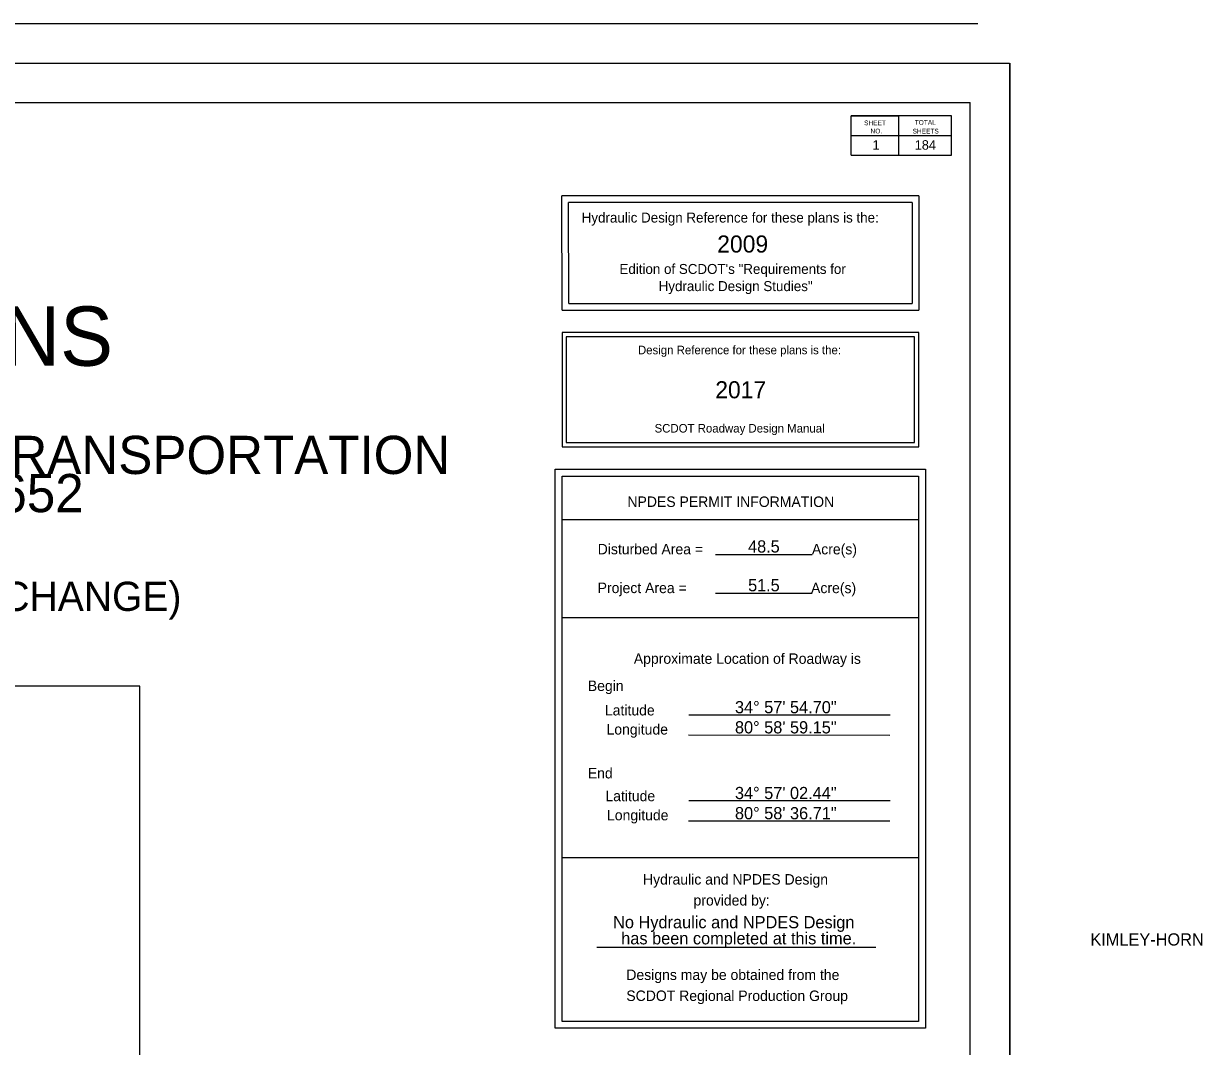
# Model space of a CAD drawing. Extents: x 1524103 to 2096450, y 1024229 to 1162569.
# Drawn here: x 2064966 to 2096450, y 1135259 to 1162569 of the extents above; entities that cross this region are included whole.
import ezdxf

# ---------------------------------------------------------------- set-up
doc = ezdxf.new("R2010")
doc.units = 0
for name, color, linetype in [('GN_TitleSheetMap', 7, 'Continuous'), ('RD_SHT_Bndy', 7, 'Continuous'), ('RD_SHT_IplotShp', 7, 'Continuous'), ('RD_SHT_Snap', 7, 'Continuous'), ('RD_SHT_TX', 7, 'Continuous'), ('RD_TX_TitleSht', 7, 'Continuous')]:
    doc.layers.add(name, color=color, linetype=linetype)

msp = doc.modelspace()

# ---------------------------------------------------------------- linework, layer by layer
at = {"layer": 'GN_TitleSheetMap'}
msp.add_lwpolyline([(2041670, 1129041), (2068070, 1129041), (2068070, 1144881), (2041670, 1144881)], close=True, dxfattribs=at)
at = {"layer": 'RD_SHT_Bndy'}
for p, q in [((2016109, 1162569), (2090454, 1162569)), ((2016109, 1161513), (2090454, 1161513)), ((2090245, 1160457), (2019494, 1160457)), ((2090249, 1116103), (2090249, 1160459)), ((2089749, 1160110), (2087066, 1160110)), ((2087066, 1159054), (2087066, 1160110)), ((2087066, 1160110), (2088334, 1160110)), ((2088334, 1160110), (2088334, 1159054)), ((2089749, 1159054), (2089749, 1160110)), ((2087068, 1159582), (2089749, 1159582)), ((2087066, 1159054), (2089749, 1159054)), ((2088877, 1157967), (2079344, 1157967)), ((2079347, 1154917), (2079344, 1157967)), ((2088877, 1157967), (2088877, 1154919)), ((2079525, 1155094), (2079521, 1157790)), ((2088701, 1157790), (2079521, 1157790)), ((2088701, 1157790), (2088700, 1155096)), ((2079347, 1154917), (2088877, 1154919)), ((2079525, 1155094), (2088700, 1155096)), ((2079350, 1149330), (2088863, 1149330)), ((2083444, 1148398), (2086031, 1148397)), ((2083444, 1147363), (2086031, 1147362)), ((2079350, 1146714), (2088863, 1146714)), ((2082731, 1144115), (2088113, 1144114)), ((2082722, 1143576), (2088104, 1143574)), ((2082731, 1141823), (2088112, 1141822)), ((2082721, 1141284), (2088103, 1141282)), ((2079350, 1140306), (2088863, 1140306)), ((2080273, 1137912), (2087726, 1137910))]:
    msp.add_line(p, q, dxfattribs=at)
for points in [[(2079165, 1150668), (2089050, 1150668), (2089050, 1135745), (2079165, 1135745)], [(2079350, 1150482), (2088863, 1150482), (2088863, 1135925), (2079350, 1135925)]]:
    msp.add_lwpolyline(points, close=True, dxfattribs=at)
at = {"layer": 'RD_SHT_IplotShp'}
msp.add_lwpolyline([(2015439, 1161513), (2091301, 1161513), (2091301, 1115047), (2015439, 1115047)], close=True, dxfattribs=at)
at = {"layer": 'RD_SHT_Snap'}
msp.add_line((2091305, 1161513), (2091305, 1115047), dxfattribs=at)
at = {"layer": 'RD_TX_TitleSht'}
for points in [[(2079346, 1151270), (2088877, 1151270), (2088877, 1154319), (2079346, 1154319)], [(2079461, 1151384), (2088762, 1151384), (2088762, 1154205), (2079461, 1154205)]]:
    msp.add_lwpolyline(points, close=True, dxfattribs=at)

# ---------------------------------------------------------------- texts
at = {"layer": 'RD_SHT_TX'}
for s, height, p in [('SHEET', 126.7, (2087414, 1159854)), ('TOTAL', 126.7, (2088766, 1159867)), ('NO.', 126.7, (2087585, 1159636)), ('SHEETS', 126.7, (2088709, 1159634)), ('PROPOSED PLANS', 1584.06, (2047814, 1153432))]:
    msp.add_text(s, height=height, dxfattribs=at).set_placement(p)
for s, height, p in [('NPDES PERMIT INFORMATION', 279.43, (2081093, 1149664)), ('Disturbed Area =                            Acre(s)', 279.43, (2080299, 1148398)), ('Project Area =                                Acre(s)', 279.43, (2080298, 1147363)), ('Approximate Location of Roadway is', 279.43, (2081264, 1145475)), ('Begin', 279.4, (2080036, 1144749)), ('Latitude', 279.4, (2080492, 1144097)), ('Longitude', 279.4, (2080535, 1143586)), ('End', 279.4, (2080035, 1142415)), ('Latitude', 279.4, (2080505, 1141807)), ('Longitude', 279.4, (2080548, 1141296)), ('Hydraulic and NPDES Design', 279.43, (2081509, 1139581)), ('             provided by:', 279.43, (2081509, 1139022)), ('Designs may be obtained from the ', 279.43, (2081064, 1137033)), ('SCDOT Regional Production Group', 279.43, (2081064, 1136473))]:
    msp.add_text(s, height=height, rotation=359.9857, dxfattribs=at).set_placement(p)
at = {"layer": 'RD_TX_TitleSht'}
for s, height, p in [(' 1', 253.4, (2087545, 1159202)), ('184', 253.4, (2088767, 1159202)), ('Hydraulic Design Reference for these plans is the:', 266.85, (2079872, 1157256)), ('2009', 457.5, (2083491, 1156455)), ('Edition of SCDOT\'s "Requirements for ', 266.85, (2080880, 1155884)), ('Hydraulic Design Studies"', 266.85, (2081927, 1155426)), ('Design Reference for these plans is the:', 228, (2081374, 1153740)), ('2017', 456, (2083440, 1152564)), ('SCDOT Roadway Design Manual', 228, (2081818, 1151650)), ('SOUTH CAROLINA DEPARTMENT OF TRANSPORTATION ', 1020, (2039229, 1150543)), ('SCDOT PROJECT ID P038652', 1020, (2047469, 1149523)), ('I-77 INTERCHANGE AT EXIT 81 (PANTHERS INTERCHANGE)', 780, (2039278, 1146887)), ('No Hydraulic and NPDES Design ', 325.99, (2080711, 1138414)), ('has been completed at this time.', 325.99, (2080928, 1137984))]:
    msp.add_text(s, height=height, dxfattribs=at).set_placement(p)
for s, height, p in [('4', 326, (2084316, 1148446)), ('8', 326, (2084557, 1148446)), ('5', 326, (2084918, 1148446)), ('.', 326, (2084798, 1148446)), ('5', 326, (2084316, 1147411)), ('1', 326, (2084557, 1147411)), ('5', 326, (2084918, 1147411)), ('.', 326, (2084797, 1147411)), ('34° 57\' 54.70"', 325.99, (2083965, 1144155)), ('80° 58\' 59.15"', 325.99, (2083965, 1143617)), ('34° 57\' 02.44"', 325.99, (2083965, 1141863)), ('80° 58\' 36.71"', 325.99, (2083965, 1141324)), ('            KIMLEY-HORN            ', 325.99, (2092004, 1137954))]:
    msp.add_text(s, height=height, rotation=359.9857, dxfattribs=at).set_placement(p)

doc.saveas('drawing.dxf')
